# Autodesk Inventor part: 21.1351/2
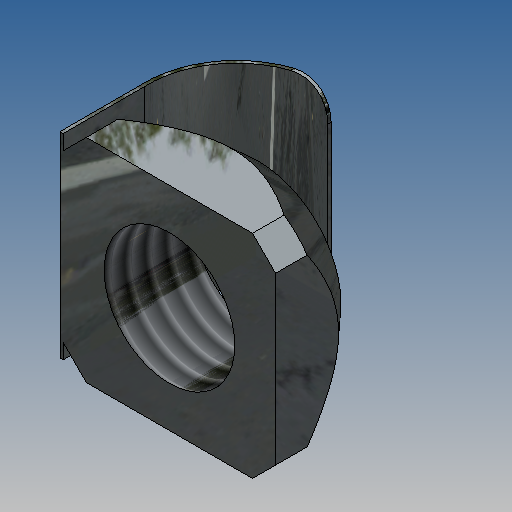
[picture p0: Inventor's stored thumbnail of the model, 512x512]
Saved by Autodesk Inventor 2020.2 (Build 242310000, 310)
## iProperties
Created: 2006-12
Part Number: 21.1351/2
Document SubType Name: Modeling
Designer: Andy Moles
Material: Steel, Mild
Density: 7.85 g/cm^3
Mass: 4.24899 g
Surface Area: 8.34272 cm^2
Volume: 0.541273 cm^3
Description: M8 SQUARE NUT POS FXG
Vendor: S
Appearance: Zinc
Title: M8 SQUARE NUT POS FXG
Author: Andy Moles
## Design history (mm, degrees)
sketch "Sketch2"
  geometry: L1 (-5.086, -6.5)-(5.086, -6.5); L2 (6.5, -5.086)-(6.5, 5.086); L3 (5.086, 6.5)-(-5.086, 6.5); L4 (-6.5, 5.086)-(-6.5, -5.086); L5 (-6.5, 6.5)-(6.5, -6.5); L6 (5.086, 6.5)-(6.5, 5.086); L7 (0, -6.5)-(0, 6.5); L8 (-6.5, 0)-(6.5, 0); L9 (-5.086, 6.5)-(-6.5, 5.086); L10 (-5.086, -6.5)-(-6.5, -5.086); L11 (5.086, -6.5)-(6.5, -5.086); C1 r 4 at (0, 0); 2 further points
  constraints: 22 end point, 6 symmetric about line, 4 parallel, 3 midpoint, 2 coincident, 2 perpendicular, 1 centre point, 1 horizontal
  dimensions: "THREAD" = 8 diameter of C1; "d3" = 45 deg angle of L3 L6 (derived); "d4" = 2 distance of L3.start L2.end
extrude "Extrusion1" new body sketch "Sketch2" distance "d5" = 5.5; taper "d6" = 0 deg
workplane "Work Plane1"
sketch "Sketch4"
  geometry: L1 (12.192, 0)-(4.192, 0) reference; L2 (8.192, 0)-(13.192, 0); L3 (16.385, 5.5)-(16.385, 3.5); L4 (13.192, 0)-(16.797, 3.952); L5 (13.192, 0)-(16.385, 0); L6 (16.385, 3.5)-(16.385, 0); L7 (16.797, 3.952)-(16.797, -0.412); L8 (16.797, -0.412)-(13.192, -0.412); L9 (13.192, -0.412)-(13.192, 0); L10 (8.192, 5.5)-(8.192, 0); L11 (16.385, 5.5)-(16.385, 0) reference; L12 (16.385, 3.5)-(17.502, 3.5); L13 (9.192, 5.5)-(16.385, 5.5) reference
  constraints: 20 end point, 6 perpendicular, 1 collinear, 1 midpoint, 1 parallel, 1 point on line
  dimensions: "d10" = 5 distance of L2.start L2.end; "d15" = 2 distance between parallel lines of L12 L13
revolve "Revolution1" sketch "Sketch4" stored, may be unused: angle "d12" = 90 deg
thread "Thread1" dims "d13" = 10, "d14" = 0
sketch "Sketch6"
  geometry: L1 (2.954, -2.535)-(2.954, 6.006); L2 (2.954, -2.535)-(2.954, -7.535); L3 (2.954, -2.535)-(3.154, -2.535); L4 (3.154, -2.535)-(3.154, -7.535); L5 (-2.646, -13.135)-(-2.646, -13.335); L6 (2.954, 0)-(2.954, -1.933); L7 (-8.632, -2.535)-(1.539, -2.535) reference; L8 (2.954, -2.535)-(2.954, -4.468) reference; A1 r 5.374 centre (-2.416, -7.766) between (-2.646, -13.135) and (2.954, -7.535); A2 r 5.574 centre (-2.416, -7.766) between (-2.646, -13.335) and (3.154, -7.535); 4 further points; 1 other entity
  constraints: 12 end point, 4 point on circle, 3 collinear, 2 centre point, 2 horizontal, 2 parallel, 2 perpendicular, 1 coincident, 3 other
  dimensions: "d25" = 5 distance of L1.start L2.end; "d23" = 0.2 distance of L1.start L3.end; "d22" = 0.2 distance of L5.start L5.end; "d21" = 10.8 distance from line of L5.end L3; "d24" = 5.37434 radius of A1
extrude "Extrusion3" join sketch "Sketch6" taper "d27" = 0 deg; stored distance "d28" = 12
fillet "Fillet2" dims "d29" = 2
body "Solid1"
